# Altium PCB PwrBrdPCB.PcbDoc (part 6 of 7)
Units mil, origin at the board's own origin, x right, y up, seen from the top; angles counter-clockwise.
Board outline 8000 x 5500 mil, 4 copper layers (Top Layer, Internal 1, Internal 2, Bottom Layer), stack 61.834 mil thick; 682 components, 380 nets, 1899 pads, 766 vias.
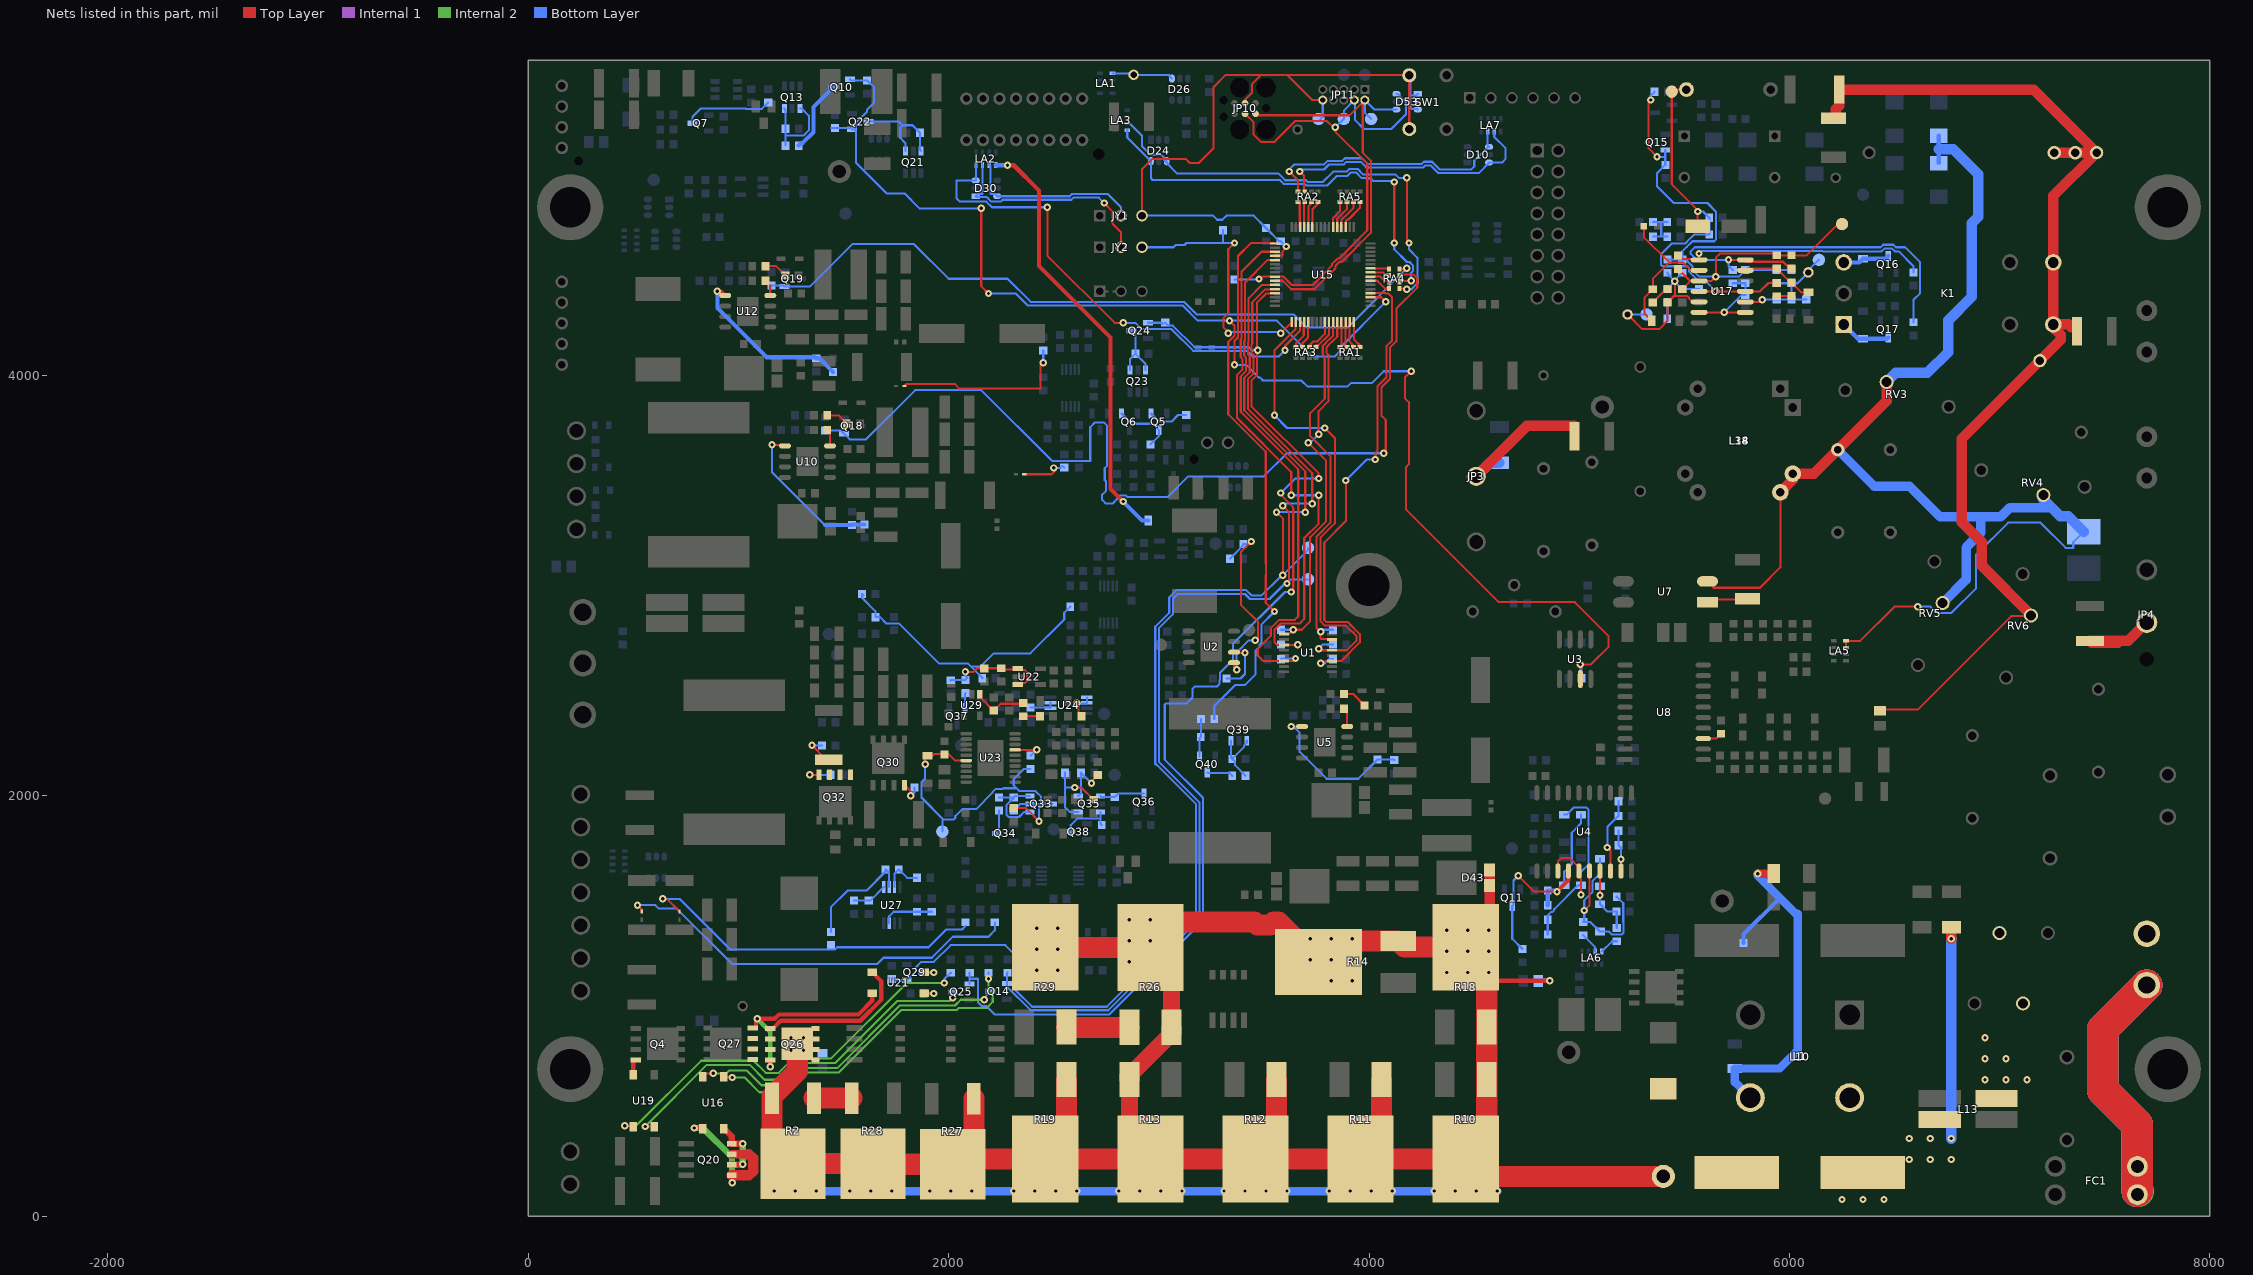
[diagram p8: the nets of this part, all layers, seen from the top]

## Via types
v1: diameter 35, hole 16, Top Layer to Bottom Layer, tented both sides, 409 vias
v2: diameter 35, hole 16, Top Layer to Bottom Layer, 348 vias
v3: diameter 35, hole 16, Top Layer to Bottom Layer, tented bottom, 5 vias
v4: diameter 60, hole 36, Top Layer to Bottom Layer, 2 vias
v5: diameter 65, hole 40.5, Top Layer to Bottom Layer, 2 vias

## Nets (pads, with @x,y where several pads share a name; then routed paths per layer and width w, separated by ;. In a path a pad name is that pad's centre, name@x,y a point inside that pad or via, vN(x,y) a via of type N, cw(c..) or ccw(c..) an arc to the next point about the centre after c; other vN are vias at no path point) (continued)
NetLA6_7: LA6.7 R16.2 | length 101.2
  Bottom Layer w10: R16.2@5018.5,1337.01 5075.75,1279.76 LA6.7@5075.75,1259.53
NetLA6_8: LA6.8 R15.1 | length 91.5
  Bottom Layer w10: LA6.8@5107.24,1259.53 5156.22,1308.5 R15.1@5178.5,1308.5
NetNT2_2: NT2.2 R133.1 | length 230.5
  Top Layer w10: NT2.2@2359.68,3530 2490,3530 2510,3550 v1(2500,3560)
  Bottom Layer w10: v1(2500,3560) 2531.38,3560 2541.38,3570 R133.1@2550,3561.38
NetNT3_2: NT3.2 R135.1 | length 847.9
  Top Layer w10: NT3.2@1789.68,3950 1799.69,3960 2028.41,3960 2051.42,3937 2437,3937 2437,4047 v1(2450,4060)
  Bottom Layer w10: v1(2450,4060) R135.1@2450,4118.5
NetNT4_2: NT4.2 R129.1 | length 1959.4
  Top Layer w10: v1(520,1480) 540,1460 NT4.2@540,1449.69
  Bottom Layer w10: v1(520,1480) 604.24,1480 620.74,1463.5 706.5,1463.5 970,1200 1660,1200 1690,1230 1920,1230 2020,1330 2190,1330 2220,1360 R129.1@2220,1398.5
NetNT5_2: NT5.2 R131.1 R209.1 | length 1690
  Top Layer w10: v1(640,1510) 659.69,1510 NT5.2@720,1449.69
  Bottom Layer w10: v1(640,1510) 720,1510 960,1270 1460,1270 1470,1280 1904.04,1280 1988.04,1364 2064,1364 R131.1@2080,1380
NetQ4_G: Q4.G U19.4 | length 75.3
  Top Layer w20: U19.4@500,673.03 500,731.92 Q4.G@511.63,743.55
NetQ5_1: Q5.1 R36.2 | length 196.6
  Bottom Layer w10: Q5.1@2962.6,3819 3001.6,3780 3060,3780 3091.5,3811.5 R36.2@3130,3811.5
NetQ5_3: Q5.3 Q6.1 R32.2 | length 295.8
  Bottom Layer w10: Q6.1@2822.6,3819 2864.98,3776.62 2877.47,3776.62 2884.09,3770 2971,3770 Q5.3@3000,3741 3000,3711.5 R32.2@2960,3671.5
NetQ7_3: Q7.3 R76.2 | length 422.1
  Bottom Layer w10: Q7.3@781,5200 781,5229.5 821.5,5270 ; 820,5270 821.5,5270 ; R76.2@1141.7,5298.5 1111,5267.8 1037.05,5267.8 1034.85,5270 821.5,5270
NetQ10_3: Q10.3 R51.2 | length 358.1
  Bottom Layer w20: R51.2@1287.13,5093.15 1287.13,5094.13 1295.83,5102.84 1303.28,5102.84 1357.13,5156.68 1357.13,5276.5 1438.87,5358.24 1438.87,5369.36 1441.37,5371.86 Q10.3@1452.49,5371.86
NetQ13_1: Q13.1 Q13.3 R40.1 R51.1 | length 427.1
  Bottom Layer w10: Q13.3@1218.23,5270 1224.13,5264.09 R40.1@1224.13,5173.15 1224.13,5143.15 ; R51.1@1224.13,5093.15 1224.13,5143.15 ; Q13.1@1293.03,5270 1300.5,5270 1335.13,5235.37 1335.13,5165.8 1310.8,5141.46 1225.82,5141.46 1224.13,5143.15
NetQ14_3: Q14.3 U16.2 | length 1604.9
  Top Layer w10: U16.2@830,663.03 830,667.28 842.72,680 v1(880,680)
  Internal 2 w10: v1(880,680) 942.62,680 956.12,693.5 1040,693.5 1110,623.5 1198.86,623.5 1280.36,705 1469.39,705 1767.39,1003 2030.38,1003 2057.38,1030 v1(2170,1030)
  Bottom Layer w10: v1(2170,1030) 2170,1040 Q14.3@2200,1070
NetQ20_1: Q20.1 Q20.3 U16.3 | length 709.1
  Top Layer w20: v1(790,420) U16.3@826.97,420 ; v1@969.47,160.53 v1(970,160)
  Top Layer w30: Q20.1@968.94,195 969.47,194.47 v1@969.47,160.53
  Top Layer w40: Q20.3@968.94,295 1050,295
  Top Layer w50: Q20.1@968.94,195 1050,195 1070,215 1070,275 1050,295
  Internal 2 w30: v1(790,420) 830,420 970,280 v1(970,160)
NetQ20_2: Q20.2 Q20.4 U16.4 | length 291
  Top Layer w30: U16.4@930,416.97 933.03,416.97 968.94,381.06 Q20.4@968.94,345 v1(1020,345) ; Q20.2@968.94,245 969.8,245.86 1019.14,245.86 v1(1020,246.72)
  Internal 2 w30: v1(1020,246.72) v1(1020,345)
NetQ21_1: Q21.1 Q21.3 Q22.3 R9.1 | length 492.7
  Bottom Layer w10: Q22.3@1619,5207.95 1762.61,5207.95 1780.56,5190 ; Q21.1@1794.79,5067.93 1794.79,5105.33 1769.99,5130.12 1769.99,5179.43 1780.56,5190 ; Q21.3@1869.59,5067.93 1863.69,5073.83 R9.1@1863.69,5154.78 1828.46,5190 1780.56,5190
NetQ23_1: Q23.1 Q23.3 Q24.3 R87.1 | length 301.9
  Bottom Layer w10: Q23.1@2862.6,4026.3 2862.6,4077.24 R87.1@2888.5,4103.15 ; Q24.3@2871,4213.15 2888.5,4195.65 R87.1@2888.5,4103.15 ; Q23.3@2937.4,4026.3 2937.4,4054.25 R87.1@2888.5,4103.15
NetQ25_3: Q25.3 U19.2 | length 1846.6
  Top Layer w10: v1(556.97,426.97) U19.2@600,426.97
  Internal 2 w10: v1(556.97,426.97) 850,720 1053.63,720 1124.13,649.5 1189.5,649.5 1270,730 1461.92,730 1755.92,1024 2004,1024 v1(2020,1040)
  Bottom Layer w10: v1(2020,1040) 2020,1065.4 Q25.3@2022,1067.4
NetQ29_3: Q29.3 U21.2 | length 98
  Top Layer w10: U21.2@1883.03,1160 v1(1930,1160)
  Bottom Layer w10: Q29.3@1879,1160 v1(1930,1160)
NetQ30_G: Q30.G R163.2 | length 111.6
  Top Layer w10: Q30.G@1790,2051.5 1820,2021.5 v1(1820,2000)
  Bottom Layer w10: v1(1820,2000) 1838.5,2018.5 R163.2@1838.5,2040
NetQ32_G: Q32.G R165.2 | length 142.1
  Top Layer w10: v1(1340,2100) 1383.42,2100 Q32.G@1383.55,2099.87
  Bottom Layer w10: v1(1340,2100) R165.2@1438.5,2100
NetQ32_S: Q32.S R171.2 R172.1 | length 152.7
  Top Layer w10: v1(1350,2240) 1408.5,2181.5 R172.1@1430,2181.5
  Bottom Layer w10: v1(1350,2240) R171.2@1398.5,2240
NetQ33_1: Q33.1 Q33.3 R177.1 R179.1 | length 373.8
  Bottom Layer w10: R179.1@2240,1992.99 R177.1@2310,1992.99 ; Q33.1@2386.85,1924.09 2359.45,1924.09 2334.65,1899.3 2285.34,1899.3 2274.64,1910 2274.64,1954.64 2310,1990 R177.1@2310,1992.99 ; Q33.3@2386.85,1998.9 2315.9,1998.9 R177.1@2310,1992.99
NetQ34_3: Q34.3 R179.2 | length 112.2
  Bottom Layer w10: Q34.3@2231,1821.5 2240,1830.5 R179.2@2240,1930
NetQ35_1: Q35.1 Q36.3 R183.1 | length 215.3
  Bottom Layer w10: Q35.1@2723.15,1998.9 2727.56,1994.49 R183.1@2790,1994.49 2806.01,2010.5 Q36.3@2930,2010.5
NetQ35_3: Q35.3 Q38.3 R190.2 | length 252.2
  Bottom Layer w10: Q38.3@2581,1830 2581,1861 2611.9,1891.9 2719.58,1891.9 2723.15,1895.47 ; Q35.3@2723.15,1924.09 2723.15,1895.47 ; R190.2@2728.5,1861.5 2723.15,1866.85 2723.15,1895.47
NetQ35_4: Q35.4 R193.2 R197.1 | length 397.6
  Top Layer w10: v1(2600,2040) 2631.5,2040 R197.1@2690,1981.5
  Bottom Layer w10: R193.2@2552.99,2110 2552.99,2040 ; v1(2600,2040) 2552.99,2040 ; Q35.4@2616.85,1924.09 2575.91,1924.09 2552.99,1947.01 2552.99,2040
NetQ35_6: Q35.6 R184.2 R187.1 | length 239.1
  Top Layer w10: v1(2680,2060) 2680,2070 2708.5,2098.5 R187.1@2710,2098.5
  Bottom Layer w10: Q35.6@2616.85,1998.9 2630,2012.05 R184.2@2630,2110 v1(2680,2060)
NetQ37_2: Q37.2 R189.1 | length 72.1
  Bottom Layer w10: Q37.2@2077.4,2417.5 2077.4,2485.9 R189.1@2080,2488.5
NetQ39_1: Q39.1 Q39.3 R142.1 R143.2 | length 313.7
  Bottom Layer w10: Q39.3@3343.55,2262.28 R142.1@3343.55,2181.34 ; R143.2@3412.44,2095.43 3412.44,2096.42 3363.15,2145.71 3363.15,2161.73 R142.1@3349.45,2175.43 R142.1@3343.55,2181.34 ; Q39.1@3418.35,2262.28 3418.35,2252.44 3404.76,2238.85 3404.76,2231.72 3354.37,2181.34 R142.1@3343.55,2181.34
NetQ40_1: Q40.1 R144.2 R146.2 | length 179.8
  Bottom Layer w10: Q40.1@3193.55,2188.43 3193.55,2274.1 R146.2@3199.45,2280 3200.75,2281.3 R144.2@3200.75,2365.22
NetQ40_3: Q40.3 R143.1 | length 124.7
  Bottom Layer w10: Q40.3@3230.95,2110.43 3232.25,2109.13 3335.75,2109.13 R143.1@3349.45,2095.43
NetR2_1: R2.1 R28.2 | length 180
  Top Layer w100: R2.1@1360,562.5 R28.2@1540,562.5
NetR26_1: R26.1 R29.2 | length 300
  Top Layer w100: R29.2@2560,899.02 R26.1@2860,899.02
NetR42_2: R42.2 R46.1 U5.5 | length 736.3
  Top Layer w10: v1(3630,2330) U5.5@3681.5,2330
  Bottom Layer w10: v1(3630,2330) 3640,2330 3670,2300 3670,2210 3798.5,2081.5 3948.5,2081.5 R46.1@4040,2172.99 4117.01,2172.99 R42.2@4120,2170
NetR45_1: R45.1 R50.1 | length 121
  Top Layer w10: R50.1@3880.28,2485 3923.51,2485 R45.1@3978.5,2430
NetR48_1: R48.1 U5.4 | length 91.5
  Top Layer w10: R48.1@3880.28,2415 3896.06,2399.21 U5.4@3896.06,2330
NetR52_2: R52.2 R74.1 R109.1 R110.2 | length 205.5
  Bottom Layer w10: R74.1@5350,4730 5390,4730 ; R109.1@5351.5,4660 5390,4660 ; R110.2@5418.5,4660 5390,4660 ; R52.2@5418.5,4730 5390,4730 ; 5390,4660 5390,4730
NetR53_2: R53.2 R59.1 | length 96.1
  Top Layer w10: R53.2@5350,4347.01 5412.99,4410 R59.1@5420,4410
NetR56_2: R56.2 R65.1 | length 70.6
  Top Layer w10: R65.1@5940,4377.01 5941.5,4378.5 R56.2@6010,4378.5
NetR57_1: R57.1 R70.1 | length 79.1
  Bottom Layer w10: R70.1@5418.5,4270 5418.5,4347.01 R57.1@5420,4348.5
NetR62_1: R62.1 R63.2 R71.2 U17.6 U17.9 | length 469.9
  Top Layer w10: U17.6@5570,4300 v1(5690,4300) U17.9@5790,4300
  Bottom Layer w10: v1(5690,4300) 5772.99,4382.99 R63.2@5790,4382.99 R62.1@5790,4438.5 R71.2@5730,4438.5
NetR85_1: R85.1 U7.1 | length 222.1
  Top Layer w10: U7.1@5636.46,2920 U7.1@5610,2920 5623.54,2933.54 R85.1@5800,2933.54
NetR88_1: R88.1 R90.2 U2.5 | length 906.6
  Top Layer w10: U2.5@3357.29,2633.5 3357.29,2612.71 v1(3370,2600) ; v1(3440,3210) 3390,3160 3390,2910 3471.53,2828.47 3471.53,2745.86 3470.93,2745.86 3465.07,2740 v1(3458.3,2740)
  Bottom Layer w10: R90.2@3338.51,3128.5 3401.5,3191.5 R88.1@3401.5,3198.5 3428.5,3198.5 v1(3440,3210) ; v1(3370,2600) 3370,2681.72 3428.28,2740 v1(3458.3,2740)
NetR89_2: R89.2 U2.6 | length 251.6
  Top Layer w10: U2.6@3357.29,2683.5 3360.79,2680 v1(3410,2680)
  Bottom Layer w10: R89.2@3321.5,2558.5 3388.5,2558.5 3410,2580 v1(3410,2680)
NetR102_1: R102.1 U8.3 | length 93.7
  Top Layer w10: U8.3@5590.12,2272.24 5650.59,2272.24 R102.1@5674.09,2295.75
NetR112_2: R112.2 R115.1 U10.5 | length 738.8
  Top Layer w10: v1(1160,3670) 1216.34,3670 U10.5@1221.34,3665
  Bottom Layer w10: v1(1160,3670) 1160,3540 1411.5,3288.5
  Bottom Layer w20: 1411.5,3288.5 R115.1@1540,3288.5 1542.99,3291.5 R112.2@1600,3291.5
NetR114_1: R114.1 R117.1 | length 112.8
  Top Layer w10: R117.1@1422.99,3807.01 R117.1@1422.99,3810 1476.61,3810 1515.63,3770.98 R114.1@1515.63,3770
NetR116_1: R116.1 U10.4 | length 80.3
  Top Layer w10: R116.1@1422.99,3740 1435.91,3727.09 U10.4@1435.91,3665
NetR120_2: R120.2 R124.1 U12.5 | length 800.9
  Top Layer w20: v1(900,4400) 917.13,4400 U12.5@937.13,4380
  Bottom Layer w20: v1(900,4400) 900,4320 1133,4087 1364.5,4087 R120.2@1370,4081.5 1385.51,4081.5 R124.1@1450,4017.01
NetR123_1: R123.1 R126.1 | length 114.1
  Top Layer w10: R126.1@1128.62,4520 1179.48,4520 1223.5,4475.98 R123.1@1223.5,4474.99
NetR125_1: R125.1 U12.4 | length 79.6
  Top Layer w10: R125.1@1128.62,4450 1151.69,4426.93 U12.4@1151.69,4380
NetR148_2: R148.2 R149.1 | length 79
  Top Layer w10: R149.1@2355.3,2378.51 R148.2@2434.31,2378.51
NetR149_2: R149.2 R150.1 U29.1 | length 263
  Top Layer w10: U29.1@2147.5,2482.93 2156,2474.43 2156,2463.55 2213.8,2405.75 R150.1@2214.78,2405.75 2215.77,2405.75 2248.06,2438.04 2355.3,2438.04 R149.2@2355.3,2441.5
NetR153_1: R153.1 U16.1 | length 1655.2
  Top Layer w10: U16.1@930,663.03 966.97,663.03 v1(970,660)
  Internal 2 w10: v1(970,660) 1030,660 1100,590 1195.05,590 1289.05,684 1478.08,684 1776.08,982 2039.07,982 2047.07,990 2180,990 2210,1020 2210,1054.79 2190,1074.79 v1(2190,1130)
  Bottom Layer w10: v1(2190,1130) 2190,1120 R153.1@2190,1158.5
NetR154_1: R154.1 U19.1 | length 1960.3
  Top Layer w10: v1(460,430) 496.97,430 U19.1@500,426.97
  Internal 2 w10: v1(460,430) 512.62,430 822.62,740 1072.13,740 1130,682.13 1192.43,682.13 1261.3,751 1441,751 1800,1110 v1(1980,1110)
  Bottom Layer w10: v1(460,430) v1@460,438.5 ; v1(1980,1110) 1980,1128.5 R154.1@2010,1158.5
NetR157_1: R157.1 U21.1 | length 95.5
  Top Layer w10: U21.1@1883.03,1060 v1(1930,1060)
  Bottom Layer w10: R157.1@1881.5,1060 v1(1930,1060)
NetR161_1: R161.1 U23.7 | length 146.2
  Top Layer w10: U23.7@2316.14,2218.78 2418.78,2218.78 v1(2420,2220)
  Bottom Layer w10: R161.1@2390,2191.5 2391.5,2191.5 v1(2420,2220)
NetR182_2: R182.2 U24.1 U24.2 | length 155.3
  Top Layer w10: v1@2600,2440 v1(2610,2440) 2610,2433.24 2617.8,2425.44 2617.8,2392.21 R182.2@2631.5,2378.5
  Bottom Layer w10: v1(2610,2440) 2655.31,2440 U24.2@2658.11,2442.8 U24.1@2658.11,2468.39
NetR192_1: R192.1 U24.6 U24.7 | length 121.6
  Bottom Layer w10: R192.1@2390,2420 2482.09,2420 U24.6@2484.88,2417.21 U24.7@2484.88,2442.8
NetR200_2: R200.2 R201.1 R202.1 R214.2 | length 1384.6
  Bottom Layer w10: R214.2@1595.8,2952.71 R214.2@1588.5,2960 1588.5,2941.5 1651.5,2878.5 R200.2@1651.5,2850 1674.04,2850 1704.84,2819.2 1764.66,2819.2 1953.86,2630 2091.72,2630 2107.22,2614.5 ; R202.1@2160,2560 2160,2561.72 2107.22,2614.5 ; R201.1@2578.5,2900 2550,2871.5 2550,2839.05 2388.95,2678 2213.96,2678 2150.46,2614.5 2107.22,2614.5
NetR204_2: R204.2 R205.1 U27.3 | length 245.4
  Bottom Layer w10: U27.3@1717.2,1393.39 1717.2,1427.2 1738.5,1448.5 R204.2@1850,1448.5 R205.1@1920,1448.5
NetR206_1: R206.1 R207.2 U27.5 | length 168.6
  Bottom Layer w10: R206.1@1550,1501.5 R207.2@1620,1501.5 1626.5,1501.5 U27.5@1691.61,1566.61
NetR208_1: R208.1 R211.2 U27.7 | length 195.1
  Bottom Layer w10: U27.7@1742.8,1566.61 1742.8,1629.8 R211.2@1762.99,1650 1802.99,1610 R208.1@1849.74,1610
NetR209_2: R209.2 R211.1 U27.6 | length 547.9
  Bottom Layer w10: R209.2@1440,1352.99 1440,1470 1520,1550 1610,1550 1700,1640 R211.1@1700,1650 1717.2,1632.8 U27.6@1717.2,1566.61
NetRA1_1: RA1.1 U15.16 | length 130.3
  Top Layer w10: U15.16@3927.64,4253.62 3927.64,4172.33 3957.24,4142.72 RA1.1@3957.24,4135.59
NetRA1_2: RA1.2 U15.15 | length 125.4
  Top Layer w10: U15.15@3907.95,4253.62 3907.95,4160.51 3925.75,4142.72 RA1.2@3925.75,4135.59
NetRA1_3: RA1.3 U15.14 | length 120.5
  Top Layer w10: U15.14@3888.27,4253.62 3888.27,4141.58 RA1.3@3894.25,4135.59
NetRA1_4: RA1.4 U15.13 | length 120.4
  Top Layer w10: RA1.4@3862.76,4135.59 3868.58,4141.42 U15.13@3868.58,4253.62
NetRA2_5: RA2.5 U15.46 | length 121.7
  Top Layer w10: RA2.5@3662.76,4824.41 3670.44,4816.72 3670.44,4707.67 U15.46@3671.73,4706.38
NetRA2_6: RA2.6 U15.45 | length 119.2
  Top Layer w10: U15.45@3691.42,4706.38 3691.42,4821.57 RA2.6@3694.25,4824.41
NetRA2_7: RA2.7 U15.44 | length 124.1
  Top Layer w10: U15.44@3711.1,4706.38 3711.1,4802.64 3725.75,4817.28 RA2.7@3725.75,4824.41
NetRA2_8: RA2.8 U15.43 | length 129
  Top Layer w10: U15.43@3730.79,4706.38 3730.79,4790.82 3757.24,4817.28 RA2.8@3757.24,4824.41
NetRA3_1: RA3.1 U15.10 | length 150.7
  Top Layer w10: RA3.1@3747.24,4135.59 3747.24,4143.2 3747.54,4143.5 3759.26,4143.5 3809.53,4193.77 U15.10@3809.53,4253.62
NetRA3_2: RA3.2 U15.9 | length 159.7
  Top Layer w10: RA3.2@3715.75,4135.59 3715.75,4142.72 3733.53,4160.5 3752.22,4160.5 3789.84,4198.12 U15.9@3789.84,4253.62
NetRA3_3: RA3.3 U15.5 | length 129.2
  Top Layer w10: RA3.3@3684.25,4135.59 3684.25,4154.25 3710.5,4180.5 3710.5,4253.02 U15.5@3711.1,4253.62
NetRA3_4: RA3.4 U15.4 | length 134
  Top Layer w10: RA3.4@3652.76,4135.59 3652.76,4152.76 3689.64,4189.64 3689.64,4251.84 U15.4@3691.42,4253.62
NetRA4_1: RA4.1 U15.26 | length 89
  Top Layer w10: U15.26@4006.38,4509.53 4092.13,4509.53 RA4.1@4094.41,4507.24
NetRA4_2: RA4.2 U15.25 | length 93.9
  Top Layer w10: U15.25@4006.38,4489.84 4066.78,4489.84 4073.19,4483.43 4086.72,4483.43 RA4.2@4094.41,4475.75
NetRA4_3: RA4.3 U15.24 | length 98.8
  Top Layer w10: U15.24@4006.38,4470.16 4054.35,4470.16 4072.57,4451.94 4086.72,4451.94 RA4.3@4094.41,4444.25
NetRA4_4: RA4.4 U15.23 | length 103.7
  Top Layer w10: U15.23@4006.38,4450.47 4039.53,4450.47 4077.24,4412.76 RA4.4@4094.41,4412.76
NetRA5_5: RA5.5 U15.38 | length 131.9
  Top Layer w10: U15.38@3829.21,4706.38 3829.21,4749.21 3862.76,4782.76 RA5.5@3862.76,4824.41
NetRA5_6: RA5.6 U15.37 | length 136.8
  Top Layer w10: U15.37@3848.9,4706.38 3848.9,4744.86 3894.25,4790.21 RA5.6@3894.25,4824.41
NetRA5_7: RA5.7 U15.36 | length 141.7
  Top Layer w10: U15.36@3868.58,4706.38 3868.58,4738.58 3925.75,4795.75 RA5.7@3925.75,4824.41
NetRA5_8: RA5.8 U15.35 | length 149.5
  Top Layer w10: U15.35@3888.27,4706.38 3888.27,4728.27 3890.05,4730.05 3890.05,4734.97 3897.08,4742 3902,4742 3957.24,4797.24 RA5.8@3957.24,4824.41
Nfiltered: C40.1 JP3.3 L19.2 | length 705.5
  Top Layer w50: JP3.3@4510,3520 4751.35,3761.35 4977.13,3761.35 L19.2@4977.13,3760
  Bottom Layer w50: JP3.3@4510,3520 4575.35,3585.35 C40.1@4620,3585.35
Nin: JP4.1 L20.1 | length 441.8
  Top Layer w50: 7562.16,2729.35 7437.78,2729.35 L20.1@7430,2737.13 7612.13,2737.13 JP4.1@7700,2825
NRESET: C67.1 D53.1 D53.3 JP10.3 JP11.10 JY1.3 R7.1 SW1.1 SW1.2 TP6.1 U15.52 | length 3701.6
  Top Layer w10: JY1.3@2920,4760 2920,4980 2970,5030 3128.28,5030 3147.78,5010.5 3190.5,5010.5 3260,5080 3260,5371.72 3318.28,5430 3486.91,5430 ; JP10.3@3410,5295 3410,5311.91 3443.75,5345.66 3443.75,5386.84 3486.91,5430 ; U15.52@3553.62,4568.58 3555.4,4570.36 3589.24,4570.36 3589.24,4589.93 3609.31,4610 v1(3605.81,4613.5) ; JP11.10@3780,5310 3730,5310 3610,5430 ; SW1.1@4191.42,5172.05 SW1.2@4191.42,5427.95 4189.37,5430 3610,5430 ; 3486.91,5430 3610,5430
  Bottom Layer w10: JY1.3@2920,4760 3258.28,4760 3277.78,4740.5 3302.22,4740.5 3321.72,4760 3451.5,4760 C67.1@3510,4701.5 3572.99,4638.5 R7.1@3580,4638.5 3605.01,4613.5 v1(3605.81,4613.5) ; TP6.1@3760,5210 3780,5230 JP11.10@3780,5310 ; SW1.2@4191.42,5427.95 4197.48,5421.89 4197.48,5331.22 ; D53.3@4231.97,5264.85 4228.68,5268.13 4204.15,5268.13 4196.26,5276.02 4196.26,5330 4197.48,5331.22 ; D53.1@4231.97,5339.65 4223.53,5331.22 4197.48,5331.22
overvoltage#: D18.K D19.K R53.1 U17.2 | length 722.2
  Top Layer w10: D18.K@5307.52,4710 5307.52,4657.9 5427.71,4537.71 ; D19.K@5344.65,4260 5310,4294.65 5310,4370 R53.1@5350,4410 5350,4460 5427.71,4537.71 ; U17.2@5570,4500 5530,4500 5501.69,4528.31 5501.69,4530.68 5494.66,4537.71 5427.71,4537.71
POS1: C70.1 L1.4 L10.4 L13.3 | length 1005.4
  Top Layer w50: v1(6770,1320) C70.1@6770,1375.35
  Bottom Layer w50: v2(6770,370) v1(6770,1320)
  other v2: 6250,80 6350,80 6450,80 6570,270 6670,270 6770,270 6570,370 6670,370
PROT.LFUSED: C31.1 GDT3.1 K1.NO L7.2 L35.1 R91.1 R92.1 RV6.2 | length 5332.1
  Top Layer w10: L35.1@6450,2410 6610,2410 7055,2855 RV6.2@7155,2855
  Top Layer w50: R91.1@6220,5230 6220,5266.46 6236.46,5282.91 6236.46,5360 6257.13,5360 7161.34,5360 C31.1@7461.34,5060 ; RV6.2@7155,2855 6914.15,3095.85 6914.15,3207.46 6820,3301.61 6820,3698.9 GDT3.1@7191.57,4070.48 7290,4168.9 7290,4192.94 7255.35,4227.59 K1.NO@7255.35,4242.36 ; v5(7260,5060) v5(7360,5060) C31.1@7461.34,5060 ; L7.2@7367.13,4228.95 7340,4228.95 7326.59,4242.36 K1.NO@7255.35,4242.36 ; K1.NO@7255.35,4242.36 K1.NO@7255.35,4537.64 7255.35,4854.01 C31.1@7461.34,5060
PROT.NPROT: C41.2 D15.K D39.A L18.4 L34.4 LA5.3 LA5.4 R77.2 RV3.2 RV4.2 RV5.2 U7.2 | length 7112.3
  Top Layer w10: U7.2@5610,3020 5640,2990 5860,2990 5956.85,3086.85 L18.4@5956.85,3443.94 ; LA5.3@6269.53,2705.75 LA5.4@6269.53,2737.24 6337.24,2737.24 6500,2900 v1(6610,2900)
  Top Layer w50: L18.4@5956.85,3443.94 6015.91,3502.99 L34.4@6015.91,3532.52 6115.67,3532.52 C41.2@6230,3646.85 6462.36,3879.21 RV3.2@6462.36,3969.06
  Bottom Layer w10: v1(6610,2900) 6670,2900 6700,2870 6770,2870 6888.22,2988.22 6888.22,3148.22 7040,3300 7194.04,3300 7314.04,3180 7350,3180 7350,3206.61 R77.2@7400,3256.61
  Bottom Layer w20: D15.K@6710,5010 6710,5075 D39.A@6710,5140
  Bottom Layer w45: RV3.2@6462.36,3969.06 6462.36,3879.21 C41.2@6230,3646.85 6403.7,3473.15 6571.13,3473.15 6717.18,3327.09 6910,3327.09 ; RV5.2@6729.06,2917.64 6840,3028.58 6840,3180.99 6910,3250.99 6910,3327.09 ; 7250,3370 7248.58,3370 7047.21,3370 7004.3,3327.09 6910,3327.09
  Bottom Layer w50: RV3.2@6462.36,3969.06 6505.68,4012.38 6655.82,4012.38 6754.69,4111.24 6754.69,4261.38 6866.68,4373.37 6866.68,4724.12 6897.5,4754.94 6897.5,4957.5 6780,5075 6710,5075 ; RV4.2@7207.64,3410.94 7248.58,3370 7288.58,3330 7326.61,3330 R77.2@7400,3256.61
PROT.RESET: D21.A K1.RESET Q17.3 | length 243
  Bottom Layer w20: K1.RESET@6257.71,4242.36 6325.43,4174.65 D21.A@6350,4174.65 6463.65,4174.65 Q17.3@6470,4181
PROT.SET: D20.A K1.SET Q16.3 | length 225.3
  Bottom Layer w20: K1.SET@6257.71,4537.64 6332.29,4537.64 D20.A@6350,4555.35 6456.35,4555.35 Q16.3@6470,4569
PV_SEL+: Q26.G Q27.G U21.4 | length 962.5
  Top Layer w20: Q27.G@1068.37,896.45 1081.36,896.45 1083.37,898.46 1083.37,929.31 1089.63,935.57 v1(1089.63,939.63) 1172.51,939.63 1192.89,960 1571.25,960 1636.97,1025.72 U21.4@1636.97,1060 ; v1(1151.63,711.63) Q26.G@1151.63,743.55
  Internal 2 w20: v1(1089.63,939.63) 1151.63,877.63 v1(1151.63,711.63)
PV_SEL-: Q26.S Q27.S U21.3 | length 735.3
  Top Layer w20: Q26.S@1151.63,893.55 1164.62,893.55 1201.07,930 1579.43,930 1680,1030.57 1680,1116.97 1649.61,1147.36 1649.61,1152.28 1641.89,1160 U21.3@1636.97,1160
PVMON_IA+: C9.1 D4.K D5.A R15.2 U4.7 | length 371.8
  Top Layer w10: v1(5098.5,1527.68) U4.7@5098.5,1642.6
  Bottom Layer w10: D4.K@5098.5,1570 v1(5098.5,1527.68) D5.A@5098.5,1485.35 5133.86,1450 C9.1@5177.01,1450 5178.5,1448.5 R15.2@5178.5,1371.5
PVMON_IA-: C10.2 D4.A D5.K R16.1 U4.6 | length 936.4
  Top Layer w10: v1(5024.02,1454.65) 5048.5,1479.14 U4.6@5048.5,1642.6
  Bottom Layer w10: D4.A@5098.5,1700.71 5098.5,1628.97 5062.5,1592.97 5062.5,1541.42 5024.02,1502.93 v1(5024.02,1454.65) 5024.02,1405.51 R16.1@5018.5,1400 5053.15,1400 D5.K@5098.5,1354.65 5140,1354.65 5153.85,1340.8 5203.16,1340.8 5210.19,1347.82 5210.19,1398.34 5209.3,1399.23 5209.3,1489.2 C10.2@5178.5,1520
PVMON_LDO: C19.1 C20.1 U4.8 | length 360
  Top Layer w10: v1(5134.02,1754.65) 5148.5,1740.16 U4.8@5148.5,1642.6
  Bottom Layer w10: v1(5134.02,1754.65) 5134.02,1851.66 C19.1@5187.01,1904.65 C20.1@5187.01,1974.65
PVMON_REF: C21.1 C22.1 U4.9 | length 196.8
  Top Layer w10: U4.9@5198.5,1642.6 v1(5198.5,1699.14)
  Bottom Layer w10: C22.1@5187.01,1834.65 C21.1@5187.01,1764.65 5198.5,1753.15 v1(5198.5,1699.14)
PVMON_V+: C15.1 D28.K D32.A Q11.3 R23.2 R60.2 U4.4 | length 1191.6
  Top Layer w10: v1(4710,1620) 4785.35,1544.65 v1(4894.02,1544.65)
  Top Layer w20: v1(4894.02,1544.65) 4948.5,1599.14 U4.4@4948.5,1642.6
  Bottom Layer w10: Q11.3@4681.42,1476.65 4681.42,1320.08 R60.2@4730,1271.5 ; Q11.3@4687.4,1482 4687.4,1597.4 v1(4710,1620) ; D28.K@4928.5,1574.65 4928.5,1639.35 4964.5,1675.35 4964.5,1825.14 5008.5,1869.14 D32.A@5008.5,1910.71
  Bottom Layer w20: R23.2@4850,1480 C15.1@4850,1550 v1@4894.02,1550
PVMON_V-: C16.1 D6.K D7.A R24.2 U4.3 U4.5 | length 1172.9
  Top Layer w10: U4.3@4898.5,1642.6 4898.5,1689.14 4914.02,1704.65 4954.02,1704.65 4998.5,1660.16 U4.5@4998.5,1642.6 5008.5,1632.6 v1(5008.5,1529.14)
  Bottom Layer w10: R24.2@4850,1340 C16.1@4850,1410 4850,1430.63 4867.68,1448.31 4873.67,1448.31 4880.7,1455.34 4880.7,1461.33 4994.01,1574.65 D6.K@5008.5,1574.65 ; D7.A@4928.5,1910.71 4940.08,1910.71 4974.02,1944.65 5033.53,1944.65 5044.5,1933.68 5044.5,1675.35 5008.5,1639.35 D6.K@5008.5,1574.65 ; v1(5008.5,1529.14) D6.K@5008.5,1574.65
PVNEG: JP1.1 L13.1 RV1.2 RV2.2
  other v2: 6930,650 7030,650 7130,650 6930,750 7030,750 6930,850
PVPOS: FC1.1 JP1.2 | length 4545.7
  Top Layer w150: FC1.1@7655.28,120 FC1.1@7655.28,236.93 7655.28,434.72 7490,600 7490,890 JP1.2@7700,1100
  Internal 1 w150: FC1.1@7655.28,118 FC1.1@7655.28,236.93 7655.28,434.72 7490,600 7490,890 JP1.2@7700,1100
  Internal 2 w150: FC1.1@7660,120 7655.28,124.72 FC1.1@7655.28,236.93 7655.28,434.72 7490,600 7490,890 JP1.2@7700,1100
  Bottom Layer w150: FC1.1@7655.28,120 FC1.1@7655.28,236.93 7655.28,434.72 7490,600 7490,890 JP1.2@7700,1100
PVPROT: C1.1 CX1.1 D8.2 D43.A1 D43.A2 L1.3 L5.1 L10.3 MECH2.1 Q26.D R2.2 R2.3 R10.1 R10.3 R11.1 R11.3 R12.1 R12.3 R13.2 R13.3 R14.2 R14.3 R18.2 R18.3 R19.1 R19.3 R26.2 R26.3 R27.1 R27.3 R28.3 R29.3 R43.2 TP23.1 | length 16883.2
  Top Layer w20: R18.3@4560,1120 v1(4860,1120)
  Top Layer w40: v2(5850,1630) C1.1@5925.35,1630
  Top Layer w50: R18.3@4460,1279.95 4573.39,1393.34 D43.A1@4573.39,1573.78 D43.A2@4573.39,1646.22
  Top Layer w80: R13.2@2860,650.98 2860,372.05 R13.3@2960,272.05 ; R13.2@2860,670 R26.2@3060,870 ; R26.3@2960,1277.95 3060,1177.95 R26.2@3060,899.02
  Top Layer w100: Q26.D@1280,820 1280,690 1160,570 R2.2@1160,562.5 1160,350 R2.3@1260,250 R28.3@1640,250 1642.5,247.5 R27.3@2020,247.5 R27.3@2044.55,272.05 ; R27.1@2120,560 2120,347.5 R27.3@2044.55,272.05 ; R29.3@2460,1277.95 R26.3@2960,1277.95 2977.95,1277.95 3100,1400 3454.64,1400 3469.14,1385.5 3530.86,1385.5 3545.36,1400 3570,1400 R14.3@3760,1210 3860,1310 R14.2@4138.94,1310 4168.98,1279.95 R18.3@4460,1279.95 4560,1179.95 4560,1120 R18.2@4560,901.02 R10.1@4560,650.98 4560,372.05 R10.3@4460,272.05 ; R19.1@2560,650.98 2560,372.05 R19.3@2460,272.05 ; R13.2@2860,650.98 R13.2@2860,670 ; R26.2@3060,870 R26.2@3060,899.02 ; R12.1@3560,650.98 3560,372.05 R12.3@3460,272.05 ; R11.1@4060,650.98 4060,372.05 R11.3@3960,272.05 ; TP23.1@5400,190 4542.05,190 R10.3@4460,272.05 ; R27.3@2044.55,272.05 R19.3@2460,272.05 ; R19.3@2460,272.05 R13.3@2960,272.05 R12.3@3460,272.05 ; R12.3@3460,272.05 R11.3@3960,272.05 ; R11.3@3960,272.05 R10.3@4460,272.05
  Bottom Layer w20: L5.1@4805.43,1120 v1(4860,1120) ; R43.2@5781.5,1300 5781.5,1341.5 5955,1515
  Bottom Layer w40: v2(1170,120) v2(1270,120) v2(1370,120) v2(1530,120) v2(1630,120) v2(1730,120) v2(1910,120) v2(2010,120) v2(2110,120) v2(2310,120) v2(2410,120) v2(2510,120) v2(2610,120) v2(2810,120) v2(2910,120) v2(3010,120) v2(3110,120) v2(3310,120) v2(3410,120) v2(3510,120) v2(3610,120) v2(3810,120) v2(3910,120) v2(4010,120) v2(4110,120) v2(4310,120) v2(4410,120) v2(4510,120) v2(4610,120) ; L1.3@5813.78,564.33 5740,638.11 CX1.1@5740,703.11 5953.11,703.11 6040,790 6040,1438.63 6031.37,1438.63 5955,1515 5850,1620 v2(5850,1630)
  other v2: 1250,790 1310,790 1250,850 1310,850 3820,1120 3920,1120 4370,1160 4470,1160 4570,1160 2420,1170 2520,1170 2860,1210 3720,1220 3820,1220 3920,1220 4370,1260 4470,1260 4570,1260 2420,1270 2520,1270 2860,1310 2960,1310 3720,1320 3820,1320 3920,1320 4370,1360 4470,1360 4570,1360 2420,1370 2520,1370 2860,1410 2960,1410
PWR_AVAIL.BIT0: R20.1 U1.3 U15.20 | length 2349.1
  Top Layer w10: v1(3770,2630) 3770,2620 3770.5,2620.5 3772.22,2620.5 3793.33,2641.61 U1.3@3824.17,2641.61 3867.38,2641.61 3956.5,2730.74 3956.5,2769.26 3898.76,2827 3797.04,2827 3787,2837.04 3787,3204.67 3890,3307.67 v1(3890,3500) ; U15.20@4006.38,4391.42 4077.12,4391.42 4079.6,4388.94 4092.39,4388.94 4110,4371.34 4110,4166.17 4082.25,4138.42 4082.25,3990.14 4039.5,3947.39 4039.5,3788.78 4040,3788.28 4040,3641.72 4030,3631.72 v1(4030,3600)
  Bottom Layer w10: v1(3770,2630) 3790,2630 3810,2650 R20.1@3828.5,2650 ; v1(3890,3500) 3990,3600 v1(4030,3600)
PWR_AVAIL.BIT1: R21.1 U1.5 U15.2 | length 2218.3
  Top Layer w10: v1(3550,3810) 3550.5,3810.5 3550.5,4120.5 3650.27,4220.27 3650.27,4251.84 U15.2@3652.05,4253.62 ; v1(3760,2700) 3767.2,2692.8 U1.5@3824.17,2692.8 3894.51,2692.8 3939.5,2737.78 3939.5,2762.22 3922.22,2779.5 3920.5,2779.5 3890,2810 3790,2810 3770,2830 3770,3229.39 3837.52,3296.91 3837.52,3702.48 v1(3790,3750)
  Bottom Layer w10: v1(3550,3810) 3610,3750 v1(3790,3750) ; v1(3760,2700) 3780,2720 R21.1@3828.5,2720
PWR_AVAIL.BIT2: R22.2 U1.7 U15.11 | length 1771.8
  Top Layer w10: U1.7@3824.17,2743.98 3821.65,2746.5 3773.5,2746.5 3770,2750 v1(3770,2780) 3750,2800 3750,3233.43 3816.3,3299.74 3816.3,3615.42 3720,3711.72 3720,3820 3789.5,3889.5 3789.5,4091.68 3779.95,4101.24 3779.95,4140.14 3816.3,4176.5 3816.5,4176.5 3829.21,4189.21 U15.11@3829.21,4253.62
  Bottom Layer w10: v1(3770,2780) 3760,2790 R22.2@3828.5,2790
PWR_AVAIL.BIT3: R30.1 U1.9 U15.12 | length 1769.6
  Top Layer w10: U1.9@3595.83,2769.57 3619.57,2769.57 v1(3640,2790) 3680,2790 3720,2830 3720,3230.71 3795.66,3306.37 3795.66,3594.34 v1(3710,3680) ; v1(3760,3720) 3760,3830 3806.5,3876.5 3806.5,4098.73 3796.95,4108.28 3796.95,4133.1 3823.34,4159.5 3823.54,4159.5 3848.9,4184.86 U15.12@3848.9,4253.62
  Bottom Layer w10: R30.1@3581.5,2790 v1(3640,2790) ; v1(3710,3680) 3720,3680 v1(3760,3720)
PWR_AVAIL.BIT4: R33.1 U1.11 U15.51 | length 2552.6
  Top Layer w10: U15.51@3553.62,4588.27 3488.27,4588.27 3393.5,4493.5 3393.5,4173.7 3389.5,4169.7 3389.5,4086.66 3398.5,4077.66 3398.5,4028.91 3372.5,4002.91 3372.5,3797.5 3630,3540 v1(3630,3430) ; v1(3661.61,2718.39) U1.11@3595.83,2718.39 3561.61,2718.39 3550,2730 3550,2790 3580,2820 3670,2820 3691.72,2841.72 3691.72,3226.46 3760,3294.75 v1(3760,3430)
  Bottom Layer w10: R33.1@3581.5,2720 3583.11,2718.39 v1(3661.61,2718.39) ; v1(3630,3430) v1(3760,3430)
PWR_AVAIL.BIT5: R35.2 U1.14 U15.53 | length 2480.7
  Top Layer w10: U15.53@3553.62,4548.9 3552.52,4550 3518.13,4550 3410.5,4442.37 3410.5,4166.66 3406.5,4162.66 3406.5,4093.7 3415.5,4084.7 3415.5,4021.86 3389.5,3995.86 3389.5,3826.93 3663.43,3553 3663.43,2853.43 3647,2837 3572.96,2837 3533,2797.04 3533,2761.28 3470.5,2698.78 3470.5,2667.78 3496.67,2641.61 U1.14@3595.83,2641.61 3638.39,2641.61 v1(3650,2653.23)
  Bottom Layer w10: R35.2@3581.5,2650 3584.72,2653.23 v1(3650,2653.23)
PWR_NRST: D30.6 JY1.2 LA2.6 | length 835.2
  Bottom Layer w10: LA2.6@2192.99,5000.94 2199.5,4994.44 2199.5,4864.42 2219.16,4864.42 D30.6@2230.98,4852.6 2576.84,4852.6 2587.24,4863 2597.75,4863 2757.34,4863 2820,4800.34 JY1.2@2820,4760
PWR_SEL.5VAUX_E\N\: Q19.1 R122.1 RA4.8 | length 3425.3
  Top Layer w10: RA4.8@4145.59,4507.24 4177.24,4507.24 v1(4180,4510)
  Bottom Layer w10: R122.1@1157.13,4428.5 1213.22,4428.5 Q19.1@1219.13,4422.6 1340,4422.6 1541.9,4624.5 1835.5,4624.5 2000,4460 2280,4460 2390,4350 3120,4350 3180,4290 3641.65,4290 3703.34,4228.31 3898.31,4228.31 v1(4180,4510)
PWR_SEL.12VAUX_E\N\: Q18.1 R86.1 RA4.7 | length 4604.8
  Top Layer w10: v1(4070,3630) 4079,3630 4079.5,3630.5 4079.5,3788.92 4059.5,3808.92 4059.5,3943.34 4099.25,3983.09 4099.25,4131.37 4130,4162.12 4130,4318.28 4229.5,4417.78 4229.5,4462.22 4212.22,4479.5 4149.34,4479.5 RA4.7@4145.59,4475.75
  Bottom Layer w10: R86.1@1411.5,3738.03 1487.06,3738.03 Q18.1@1502.5,3722.6 1529.24,3695.85 1607.22,3695.85 1841.37,3930 2155.2,3930 2491.53,3593.67 2673.67,3593.67 2673.67,3753.67 2696.62,3776.62 2737.47,3776.62 2754.09,3760 2754.09,3569.63 2743,3558.54 2743,3501.46 2747.78,3496.68 2747.78,3449.5 2730.5,3432.22 2730.5,3407.78 2747.78,3390.5 2780.5,3390.5 2800.5,3410.5 2800.5,3412.22 2817.78,3429.5 2842.22,3429.5 2850,3421.72 3041.72,3421.72 3140,3520 3500,3520 3610,3630 v1(4070,3630)
PWR_SEL.COMP_PWRD: Q24.1 Q25.1 R98.1 R156.2 U15.61 | length 5872.9
  Top Layer w10: U15.61@3553.62,4391.42 3551.84,4389.64 3510.89,4389.64 3466.5,4345.25 3466.5,4000.74 3440.5,3974.74 3440.5,3853.74 3760,3534.24 v1(3760,3510) ; v1(3580,3440.86) 3580,3431.72 3639.5,3372.22 3639.5,2980.5 3640,2980 v1(3630,2970)
  Bottom Layer w10: Q25.1@2100,1104.8 2100,1130 ; R156.2@2100,1158.5 2100,1130 ; Q24.1@2949,4250.55 3014.1,4250.55 R98.1@3020,4244.65 ; R98.1@3030,4251.5 3044.5,4237 3067.04,4237 3170.04,4134 3428.12,4134 3442.12,4120 v1(3470,4120) ; v1(3580,3440.86) 3649.14,3510 v1(3760,3510) ; v1(3630,2970) 3600,2970 3353,2723 3353,2647.25 3290.8,2585.05 3290.8,2551.89 3289.21,2550.3 3289.21,2533.85 3280,2524.64 3280,2519.63 3170.13,2519.63 3160,2509.5 3160,2467.8 3132.2,2440 3034.27,2440 3028.42,2434.14 3028.42,2172.57 3210,1990.99 3210,1406.17 2763.83,960 2220,960 2179.5,1000.5 2157.78,1000.5 2140,1018.28 2140,1130 2100,1130
PWR_SEL.MAINBRD_EN: Q10.1 Q22.1 R1.1 R47.2 R144.1 U15.19 | length 6109.3
  Top Layer w10: v1(2155.2,4795) 2155.2,4424.8 v1(2190,4390) ; v1(3336.5,4260.46) 3359.5,4237.46 3359.5,4187.78 3330.5,4158.78 3330.5,3815.46 3508.67,3637.29 3508.67,3105 3509.5,3104.17 3509.5,3047.78 3508.67,3046.95 3508.67,2918.5 v1(3550.16,2877.01) ; U15.19@4006.38,4371.73 4058.27,4371.73 v1(4080,4350)
  Bottom Layer w10: R1.1@1441.5,5176.45 R1.1@1460,5176.45 Q22.1@1535.1,5176.45 ; Q10.1@1530.49,5409.26 1536.4,5403.35 R47.2@1611.49,5403.35 1612.48,5403.35 1645.75,5370.09 1645.75,5298.35 1611.49,5264.09 1611.49,5253.53 1559.62,5201.66 1559.62,5178.05 Q22.1@1552.12,5170.55 ; Q22.1@1541,5170.55 Q22.1@1552.12,5170.55 ; v1(2155.2,4795) 1860.76,4795 1790.48,4865.28 1705.32,4865.28 1559.62,5010.98 1559.62,5163.05 Q22.1@1552.12,5170.55 ; v1(2190,4390) 2320,4390 2377,4333 3112.96,4333 3185.5,4260.46 v1(3336.5,4260.46) 3561.26,4260.46 3730.72,4091 3838.28,4091 3859.5,4112.22 3859.5,4129.5 v1(4080,4350) ; R144.1@3263.74,2365.22 3263.74,2427.64 3362.6,2526.5 3408.22,2526.5 3460.74,2579.02 3460.74,2691.24 3479.5,2710 3479.5,2719.48 3487.8,2727.78 3487.8,2759.32 3487.8,2814.66 v1(3550.16,2877.01)
PWR_SEL.SEL_AC: Q14.1 R155.2 TP29.1 U15.60 | length 5308.8
  Top Layer w10: U15.60@3553.62,4411.1 3551.84,4409.32 3506.53,4409.32 3444.5,4347.29 3444.5,4152.57 3440.5,4148.57 3440.5,4107.78 3449.5,4098.78 3449.5,4007.78 3423.5,3981.78 3423.5,3841.01 3730,3534.51 v1(3730,3390) ; v1(3590,3380) 3620,3350 3620,3020 v1(3610,3010)
  Bottom Layer w10: R155.2@2280,1160 R155.2@2280,1158.5 2278,1156.5 Q14.1@2278,1107.4 2278,1092 2390,980 2759.79,980 3193,1413.21 3193,1968.88 3000,2161.88 3000,2797.67 3066.5,2864.17 3066.5,2936.5 3090,2960 3410.2,2960 3433.7,2936.5 3526.5,2936.5 3600,3010 v1(3610,3010) 3630,3030 TP29.1@3710,3030 ; v1(3590,3380) 3600,3390 v1(3730,3390)
PWR_SEL.SEL_PV: Q29.1 R158.2 TP28.1 U15.59 | length 6099.8
  Top Layer w10: U15.59@3553.62,4430.79 3490.79,4430.79 3427.5,4367.5 3427.5,4159.61 3423.5,4155.61 3423.5,4100.74 3432.5,4091.74 3432.5,4014.82 3406.5,3988.82 3406.5,3833.97 3696.76,3543.71 v1(3696.76,3350) ; v1(3560,3350) 3590,3320 v1(3590,3050)
  Bottom Layer w10: R158.2@1730,1128.5 1735.9,1122.6 Q29.1@1801,1122.6 1843.38,1164.98 1843.38,1183.38 1870,1210 1930,1210 2010,1290 2270,1290 2320,1240 2320,1074.04 2397.04,997 2752.75,997 3176,1420.25 3176,1961.84 2989.72,2148.12 2987.84,2148.12 2983,2152.96 2983,2804.71 3049.5,2871.21 3049.5,2943.54 3085.96,2980 3414.24,2980 3440.74,2953.5 3489.26,2953.5 3576.5,3040.74 3576.5,3046.5 3580,3050 v1(3590,3050) 3710,3170 TP28.1@3710,3180 ; v1(3560,3350) 3560.5,3350.5 3561,3350 v1(3696.76,3350)
PWR_SELECT: D30.1 JY2.2 LA2.7 | length 1056.7
  Top Layer w10: v1(2740,4820) 2780.5,4779.5 2780.5,4720.5 2820,4681 JY2.2@2820,4610
  Bottom Layer w10: LA2.7@2161.5,5000.94 2160.5,4999.95 2160.5,4864.42 2140.84,4864.42 D30.1@2129.02,4852.6 2133.61,4848 2182.31,4848 2203.29,4827.02 2247.49,4827.02 2256.07,4835.6 2583.88,4835.6 2594.28,4846 2604.79,4846 2714,4846 v1(2740,4820)
PWR_WAKE: D30.3 LA2.8 U15.3 | length 2435.2
  Top Layer w10: v1(2470,4800) 2470,4570 2790,4250 v1(2830,4250) ; v1(3600,4120) 3600,4140 3671.73,4211.73 U15.3@3671.73,4253.62
  Bottom Layer w10: LA2.8@2130,5000.94 2130,4928.38 D30.3@2129.02,4927.4 2037.4,4927.4 2037.4,4842.6 2053.5,4826.5 2179.77,4826.5 2206.27,4800 v1(2470,4800) ; v1(2830,4250) 2887.24,4250 2917.24,4220 3060,4220 3163,4117 3421.08,4117 3448.08,4090 3570,4090 v1(3600,4120)
ref_high: C74.1 R54.2 R57.2 R59.2 R93.2 R94.1 TP7.1 TP24.1 U17.5 | length 952.7
  Top Layer w10: TP7.1@5230,4290 5300,4220 5380,4220 5420,4260 R59.2@5420,4347.01 5450.7,4377.71 ; v1(5455,4448.03) 5455,4382.01 5450.7,4377.71 ; U17.5@5570,4350 5539.3,4350 5521.69,4367.61 5521.69,4370.68 5514.66,4377.71 5450.7,4377.71
  Bottom Layer w10: TP7.1@5230,4290 TP24.1@5320,4290 ; R57.2@5420,4411.5 5420,4413.03 v1(5455,4448.03) ; R54.2@5420,4488.5 5420,4483.03 v1(5455,4448.03) ; R93.2@5490,4488.5 5455,4453.5 v1(5455,4448.03) ; C74.1@5570,4411.5 R94.1@5490,4411.5 5455,4446.5 v1(5455,4448.03)
ref_low: C75.1 R66.2 R69.1 R95.2 R96.1 TP8.1 TP25.1 U17.10 | length 623.8
  Top Layer w10: U17.10@5790,4350 5860,4350 v1(5870,4360)
  Bottom Layer w10: v1(5870,4360) 5871.5,4361.5 R96.1@5940,4361.5 R69.1@6010,4361.5 ; R95.2@5940,4438.5 R66.2@6010,4438.5 ; C75.1@6080,4361.5 R69.1@6010,4361.5 ; TP25.1@6140,4550 6090,4500 TP8.1@6090,4490 6038.5,4438.5 R66.2@6010,4438.5 ; R69.1@6010,4361.5 R66.2@6010,4438.5
reset: C37.2 R64.1 R71.1 U17.14 | length 2020.5
  Top Layer w10: v1(5710,4550) U17.14@5790,4550 5790,4540.8 5969.2,4540.8 6001.5,4508.5 R64.1@6010,4508.5
  Bottom Layer w10: R71.1@5730,4501.5 5710,4521.5 v1(5710,4550) 5558.28,4550 5530,4578.28 5530,4590 5550,4610 6433.87,4610 6445.49,4621.62 6494.51,4621.62 6506.13,4610 6550,4610 6621.69,4538.31 6621.69,4391.69 6590,4360 C37.2@6590,4252.99
RTC_INT: R8.1 U3.3 U15.49 | length 3895.6
  Top Layer w10: v1(3360,4050) 3360,4164.24 3376.5,4180.74 3376.5,4568.22 3437.78,4629.5 3551.76,4629.5 U15.49@3553.62,4627.64 ; v1(4200,4020) 4170.5,3990.5 4170.5,3891.22 4189.5,3872.22 4189.5,3577.57 4176.5,3564.57 4176.5,3361.54 4616.54,2921.5 4978.5,2921.5 5140,2760 5140,2710 5055,2625 v1(5005,2625) U3.3@5005,2555.51
  Bottom Layer w10: v1(3360,4050) 3415.96,4050 3476.46,3989.5 3482.22,3989.5 3495.72,3976 3678.24,3976 3707.74,3946.5 3896.3,3946.5 3913.3,3963.5 4013.3,3963.5 4069.8,4020 v1(4200,4020) ; v1(5005,2625) 5011.5,2618.5 R8.1@5011.5,2560
sense_prot: C35.+ C72.1 D17.K R65.2 R108.1 TP22.1 U17.4 U17.11 | length 1970.9
  Top Layer w10: D17.K@5540,5360 D17.K@5510,5360 5450,5360 TP22.1@5440,5350 5440,4910 5563.39,4786.61 v1(5563.39,4780) C35.+@5563.39,4710 ; U17.4@5570,4400 v1(5650,4400) U17.11@5790,4400 5860,4400 5900,4440 R65.2@5940,4440
  Bottom Layer w10: v1(5563.39,4780) 5588.5,4780 R108.1@5618.5,4750 C72.1@5618.5,4670 5545.96,4670 5512.2,4636.24 5512.2,4635.34 5505.17,4628.31 5441.46,4628.31 5388.32,4575.17 5388.32,4527.82 5395.34,4520.8 5409.2,4520.8 5410.8,4519.2 5514.66,4519.2 5521.69,4512.18 5521.69,4495.77 5564.45,4453 5597,4453 v1(5650,4400)
set: C36.2 R58.1 U17.1 | length 1234.8
  Top Layer w10: R58.1@5470,4570 5485.29,4554.71 5565.29,4554.71 U17.1@5570,4550 v1(5570,4580)
  Bottom Layer w10: v1(5570,4580) 5581.53,4591.53 6157.2,4591.53 6158.73,4590 6437.91,4590 6452.53,4604.62 6487.47,4604.62 6502.09,4590 6520,4590 6590,4520 C36.2@6590,4490
SWCLK: D53.6 JP10.4 JP11.4 R147.1 TP2.1 U15.57 | length 2565
  Top Layer w10: JP10.4@3410,5245 3451.25,5203.75 3451.25,5145.66 3486.91,5110 3550,5110 3550,5112.33 3647.67,5210 3800,5210 3830,5180 v1(3840,5180) 3840,5160 3991.56,5008.44 3991.56,4690.55 3857.51,4556.5 3850.74,4556.5 3823.5,4529.26 3823.5,4522.49 3731.51,4430.5 3632.79,4430.5 3593.14,4470.16 U15.57@3553.62,4470.16 3494.92,4470.16 3483.26,4458.5 v1(3476.5,4458.5)
  Bottom Layer w10: R147.1@3360,4456.78 3474.78,4456.78 v1(3476.5,4458.5) ; v1(3840,5180) TP2.1@3880,5220 3880,5260 JP11.4@3930,5310 3932.51,5307.49 3932.51,5215.9 3976.24,5172.18 4106.03,5172.18 4175.26,5241.41 4175.26,5300.3 4135.91,5339.65 D53.6@4130,5339.65
SWDIO: D53.4 JP10.2 JP11.2 TP1.1 U15.58 | length 2055.5
  Top Layer w10: JP10.2@3460,5245 3460,5237.75 3907.75,5237.75 JP11.2@3970,5300 ; U15.58@3553.62,4450.47 3588.78,4450.47 3629.25,4410 3740,4410 3840.5,4510.5 3840.5,4522.22 3857.78,4539.5 3869.5,4539.5 4008.56,4678.56 4008.56,5021.44 3970,5060 JP11.2@3970,5300 ; JP11.2@3980,5310 JP11.2@3970,5300
  Bottom Layer w10: TP1.1@4010,5220 3980,5250 JP11.2@3980,5310 4025.15,5264.85 D53.4@4130,5264.85
TEST_MODE: JY2.3 R151.2 U15.1 | length 1301.5
  Top Layer w10: v1(3330,4200) 3330,4206.76 3307,4229.76 3307,4272.67 3330.5,4296.17 3330.5,4600.5 v1(3360,4630) ; v1(3580,4200) 3580,4201.26 U15.1@3632.36,4253.62
  Bottom Layer w10: JY2.3@2920,4610 3070,4610 3080.5,4620.5 3122.22,4620.5 3131.72,4630 3303.77,4630 ; R151.2@3305,4690.55 3305,4631.23 3303.77,4630 ; v1(3330,4200) 3336.5,4206.5 3573.5,4206.5 v1(3580,4200) ; v1(3360,4630) 3303.77,4630
TP15: D26.4 LA1.5 TP15.1 | length 297.6
  Bottom Layer w10: LA1.5@2779.53,5437.24 2872.76,5437.24 TP15.1@2880,5430 3051.61,5430 3051.61,5423.07 D26.4@3062.6,5412.08
UART2_RXD: D10.4 LA7.7 RA2.4 | length 1261.6
  Top Layer w10: v1(3620,4970) 3662.76,4927.24 RA2.4@3662.76,4875.59
  Bottom Layer w10: v1(3620,4970) 3620,4980 3643,5003 3785.28,5003 3802.78,5020.5 3872.61,5020.5 3885.36,5033.25 3966.95,5033.25 3993.7,5006.5 4250.74,5006.5 4260.74,5016.5 4299.26,5016.5 4335.26,4980.5 4486.96,4980.5 4500.5,4994.04 4500.5,5021.61 4566.3,5087.4 D10.4@4570.98,5087.4 4564.25,5094.13 LA7.7@4564.25,5160.47
UART2_TXD: D10.6 LA7.6 RA2.3 | length 1315.4
  Top Layer w10: v1(3670,4970) 3690.5,4949.5 3690.5,4879.34 RA2.3@3694.25,4875.59
  Bottom Layer w10: v1(3670,4970) 3679.5,4979.5 3785.82,4979.5 3809.82,5003.5 3879.66,5003.5 3892.4,5016.25 3959.91,5016.25 3986.66,4989.5 4004.34,4989.5 4004.66,4989.19 4257.47,4989.19 4267.78,4999.5 4292.22,4999.5 4328.22,4963.5 4523.5,4963.5 4570.98,5010.98 D10.6@4570.98,5012.6 4632.6,5012.6 4650,5030 4650,5080 4595.75,5134.25 LA7.6@4595.75,5160.47
UART_DAQ2PWR: D24.6 LA3.8 RA4.6 | length 2066.7
  Top Layer w10: v1(4120,4630) v1(4120,4920) ; RA4.6@4145.59,4444.25 4151.34,4450 v1(4200,4450)
  Bottom Layer w10: LA3.8@2850,5167.01 2850,5131.61 D24.6@2962.6,5019.02 2962.6,4937.4 2970,4930 3575.96,4930 3594.46,4911.5 3692.74,4911.5 3700.74,4903.5 3801.78,4903.5 3847.78,4949.5 3897.78,4949.5 3913.53,4965.25 3938.78,4965.25 3965.53,4938.5 3983.22,4938.5 3983.53,4938.19 4007.57,4938.19 4021.26,4924.5 4115.5,4924.5 v1(4120,4920) ; v1(4120,4630) 4120,4600 4180.5,4539.5 4192.22,4539.5 4209.5,4522.22 4209.5,4497.78 4200,4488.28 v1(4200,4450)
UART_PWR2DAQ: D24.4 LA3.7 RA4.5 | length 2149.2
  Top Layer w10: RA4.5@4145.59,4412.76 4177.24,4412.76 v1(4180,4410) ; v1(4180,4940) 4180,4640 v1(4190,4630)
  Bottom Layer w10: LA3.7@2850,5198.5 2861.5,5198.5 2920.02,5139.98 2920.02,5089.48 2959,5050.5 2973.19,5050.5 2973.7,5050 2988.9,5050 2989.4,5050.5 3010.6,5050.5 3025.58,5035.52 3025.58,5024.42 3030.98,5019.02 D24.4@3037.4,5019.02 3037.4,5010.88 3088.28,4960 3570,4960 3601.5,4928.5 3699.78,4928.5 3707.78,4920.5 3780.5,4920.5 3829.5,4969.5 3893.74,4969.5 3906.49,4982.25 3945.82,4982.25 3972.57,4955.5 3990.26,4955.5 3990.57,4955.19 4126.53,4955.19 4141.72,4940 v1(4180,4940) ; v1(4180,4410) 4201.72,4410 4230,4438.28 4230,4560 4190,4600 v1(4190,4630)
undervoltage#: D22.K R56.1 R67.1 U17.13 | length 350.4
  Top Layer w10: U17.13@5790,4500 5798.5,4508.5 R67.1@5940,4508.5 6007.01,4441.5 R56.1@6010,4441.5 6056.14,4395.35 D22.K@6090,4395.35
VBAT_UNREG: D2.A LA2.5 | length 2058.6
  Top Layer w20: v1(2280,5000) 2310,5000 2430,4880 2430,4520 2770,4180 2770,3460 v1(2830,3400)
  Bottom Layer w20: LA2.5@2224.49,5000.94 2225.43,5000 v1(2280,5000) ; v1(2830,3400) 2920,3310 D2.A@2950,3310
VCC_AUX3: C133.1 C134.1 C135.1 D48.A Q33.2 Q33.5 R159.2 R161.2 R177.2 R188.2 R189.2 TP32.1 U22.1 U22.3 U23.16 | length 2266.3
  Top Layer w10: v1(1888.5,2149.56) 1888.5,2179.8 D48.A@1900,2191.3 ; D48.A@1920,2186.85 1931.65,2198.5 2000,2198.5 2030.9,2167.6 U23.16@2083.86,2167.6 ; v1(2080,2590) 2118.82,2590 2135.31,2606.5 C134.1@2170,2606.5 ; C134.1@2180,2606.89 C135.1@2250,2606.89 2255.08,2601.81 U22.1@2324.73,2601.81 ; R159.2@2310,1941.5 2368.5,1941.5 v1(2430,1880) ; U22.1@2327.73,2604.81 2334.54,2598 2363,2598 2373,2588 2373,2546.9 2362.11,2536.01 2335.01,2536.01 U22.3@2329.01,2530.01
  Bottom Layer w10: v1(1888.5,2149.56) 1888.5,2082.36 1870.8,2064.66 1870.8,1992.35 1975.34,1887.8 ; TP32.1@1970,1830 1970,1882.46 1975.34,1887.8 ; R188.2@2010,2550 2011.5,2551.5 R189.2@2080,2551.5 2090,2561.49 2080,2571.49 v1(2080,2590) ; R177.2@2310,1930 2341.5,1961.5 Q33.2@2386.85,1961.5 2440,1961.5 ; R161.2@2390,2128.5 2358.5,2128.5 2310,2080 2310,2050 2323.65,2036.35 ; v1(2430,1880) 2430,1951.5 2440,1961.5 ; Q33.5@2493.15,1961.5 2440,1961.5 ; 1975.34,1887.8 2024.66,1887.8 2031.69,1894.83 2031.69,1903.18 2065.13,1936.62 2130.71,1936.62 2208.31,2014.22 2208.31,2016.66 2224.65,2033 2257.04,2033 2260.4,2036.35 2323.65,2036.35 ; 2323.65,2036.35 2337.29,2022.71 2413.47,2022.71 2440,1996.18 2440,1961.5
Vcc_prot: C34.1 Q15.2 R54.1 R55.2 R58.2 R62.2 R64.2 R66.1 R67.2 R93.1 R95.1 R106.1 TP13.1 U17.3 | length 2932.4
  Top Layer w10: v1(5340,5310) 5330,5300 5330,5080 v1(5370,5040) ; R58.2@5470,4507.01 5527.01,4450 U17.3@5530,4450 ; R55.2@5490,4410 U17.3@5530,4450 ; TP13.1@6250,4720 6230,4720 6081.5,4571.5 R64.2@6010,4571.5 R67.2@5940,4571.5 5931.5,4580 5670,4580 5650,4560 v1(5650,4470) 5630,4450 U17.3@5570,4450 U17.3@5530,4450
  Bottom Layer w10: v1(5340,5310) 5340,5331.5 R106.1@5358.5,5350 ; v1(5370,5040) 5409,5040 ; Q15.2@5409,5072.6 5409,5040 ; R54.1@5420,4551.5 R93.1@5490,4551.5 ; R66.1@6010,4501.5 R95.1@5940,4501.5 R62.2@5790,4501.5 5758.5,4470 v1(5650,4470) 5571.5,4470 5538.69,4502.81 5538.69,4519.22 5506.41,4551.5 R93.1@5490,4551.5 ; 5409,5040 5409,5002.5 C34.1@5410,5001.5 5370,4961.49 5370,4900 5450,4820 5610,4820 5650,4780 5650,4646.14 5642.18,4638.32 5541.68,4638.32 5540,4640 5529.2,4629.2 5529.2,4628.3 5512.21,4611.31 5511.31,4611.31 5490,4590 R93.1@5490,4551.5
